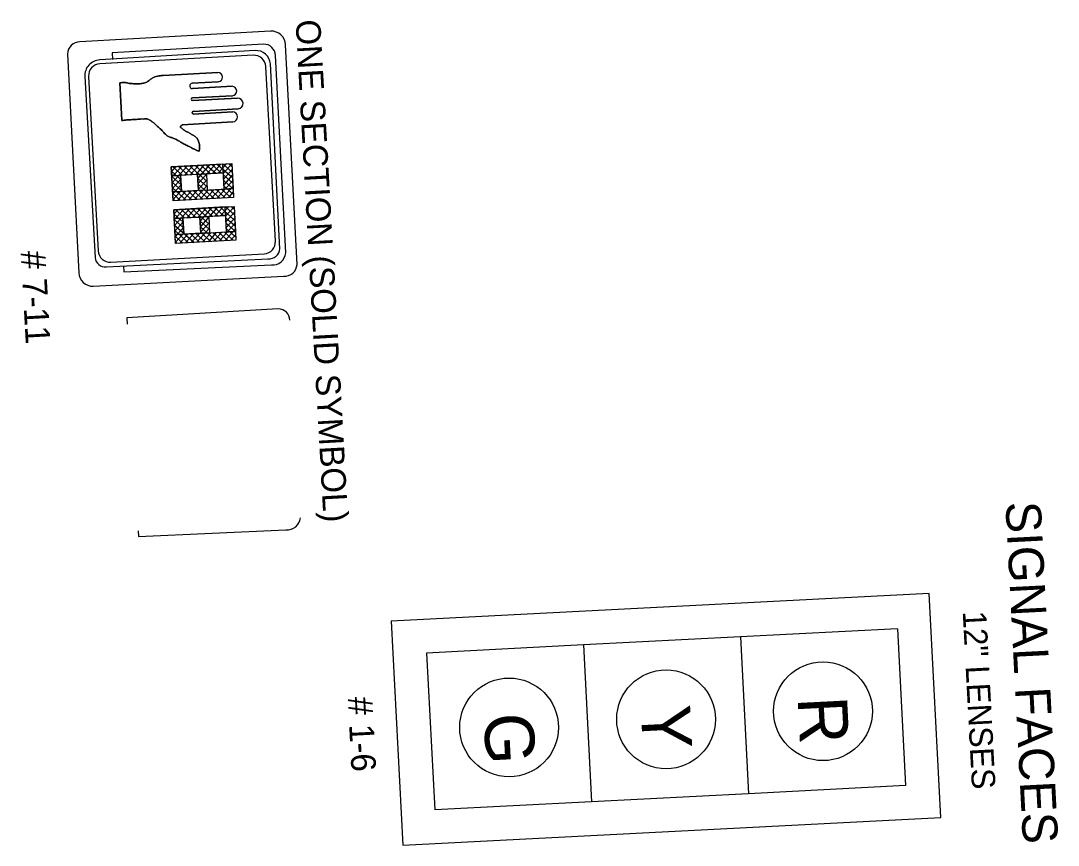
# Model space of a CAD drawing. Extents: x -218554 to 420114, y -565956 to -483460.
# Drawn here: x -218285.8 to -218207.2, y -484168.8 to -484106.3 of the extents above; entities that cross this region are included whole.
import ezdxf

# ---------------------------------------------------------------- set-up
doc = ezdxf.new("R2010")
doc.units = 0
for name, color, linetype in [('C-ANNO-TEXT', 7, 'Continuous'), ('Level 1', 7, 'Continuous'), ('Level 61', 7, 'Continuous')]:
    doc.layers.add(name, color=color, linetype=linetype)

msp = doc.modelspace()

# ---------------------------------------------------------------- linework, layer by layer
at = {"layer": 'Level 1'}
for p, q in [((-218266.858, -484107.089), (-218281.297, -484107.896)), ((-218264.85, -484124.763), (-218265.721, -484108.12)), ((-218282.226, -484108.821), (-218281.371, -484125.397)), ((-218268.029, -484108.558), (-218279.793, -484109.264)), ((-218265.704, -484123.89), (-218266.495, -484108.923)), ((-218266.149, -484123.569), (-218266.874, -484109.566)), ((-218280.924, -484110.527), (-218280.144, -484124.236)), ((-218274.981, -484110.441), (-218270.845, -484110.213)), ((-218270.845, -484110.213), (-218274.981, -484110.441)), ((-218278.123, -484113.841), (-218278.279, -484111.01)), ((-218278.264, -484110.994), (-218278.124, -484113.853)), ((-218270.814, -484110.923), (-218272.786, -484111.031)), ((-218272.786, -484111.031), (-218270.814, -484110.923)), ((-218272.764, -484111.431), (-218269.772, -484111.266)), ((-218269.772, -484111.266), (-218272.764, -484111.431)), ((-218272.779, -484112.349), (-218269.354, -484112.16)), ((-218269.354, -484112.16), (-218272.779, -484112.349)), ((-218269.741, -484111.977), (-218272.775, -484112.144)), ((-218272.775, -484112.144), (-218269.741, -484111.977)), ((-218272.707, -484113.367), (-218269.722, -484113.203)), ((-218269.722, -484113.203), (-218272.707, -484113.367)), ((-218269.301, -484112.975), (-218272.702, -484113.162)), ((-218272.702, -484113.162), (-218269.301, -484112.975)), ((-218278.126, -484113.855), (-218278.123, -484113.841)), ((-218269.705, -484113.964), (-218273.547, -484114.175)), ((-218273.547, -484114.175), (-218269.705, -484113.964)), ((-218271.049, -484117.19), (-218272.344, -484118.636)), ((-218270.624, -484117.167), (-218271.253, -484117.869)), ((-218270.863, -484117.18), (-218269.742, -484118.184)), ((-218270.2, -484117.144), (-218270.829, -484117.846)), ((-218270.438, -484117.157), (-218269.766, -484117.759)), ((-218269.799, -484117.147), (-218270.428, -484117.85)), ((-218270.014, -484117.133), (-218269.789, -484117.335)), ((-218274.355, -484117.686), (-218273.652, -484118.315)), ((-218274.021, -484117.354), (-218274.352, -484117.724)), ((-218273.596, -484117.331), (-218274.329, -484118.149)), ((-218273.172, -484117.307), (-218274.306, -484118.573)), ((-218274.259, -484117.367), (-218273.557, -484117.996)), ((-218273.835, -484117.344), (-218273.133, -484117.973)), ((-218273.41, -484117.32), (-218272.708, -484117.949)), ((-218272.747, -484117.284), (-218273.376, -484117.986)), ((-218272.986, -484117.297), (-218271.686, -484118.462)), ((-218272.323, -484117.261), (-218272.952, -484117.963)), ((-218272.561, -484117.274), (-218271.709, -484118.037)), ((-218271.898, -484117.237), (-218272.527, -484117.94)), ((-218272.382, -484117.932), (-218272.315, -484119.162)), ((-218271.473, -484117.214), (-218272.367, -484118.212)), ((-218272.137, -484117.25), (-218271.434, -484117.879)), ((-218271.717, -484117.895), (-218271.649, -484119.125)), ((-218271.712, -484117.227), (-218271.01, -484117.856)), ((-218271.287, -484117.204), (-218270.585, -484117.833)), ((-218270.421, -484117.979), (-218269.719, -484118.608)), ((-218269.776, -484117.572), (-218270.405, -484118.274)), ((-218274.331, -484118.11), (-218273.629, -484118.739)), ((-218274.308, -484118.535), (-218272.831, -484119.858)), ((-218273.653, -484118.296), (-218274.282, -484118.998)), ((-218273.63, -484118.72), (-218274.259, -484119.423)), ((-218272.365, -484118.257), (-218271.662, -484118.886)), ((-218272.341, -484118.682), (-218271.132, -484119.764)), ((-218271.691, -484118.358), (-218272.32, -484119.061)), ((-218269.729, -484118.421), (-218270.922, -484119.752)), ((-218270.398, -484118.404), (-218269.696, -484119.033)), ((-218269.753, -484117.996), (-218270.382, -484118.699)), ((-218274.284, -484118.959), (-218273.255, -484119.881)), ((-218274.261, -484119.384), (-218273.68, -484119.904)), ((-218273.606, -484119.145), (-218274.235, -484119.847)), ((-218273.265, -484119.214), (-218273.894, -484119.916)), ((-218272.84, -484119.19), (-218273.469, -484119.893)), ((-218273.109, -484119.205), (-218272.406, -484119.834)), ((-218272.416, -484119.167), (-218273.045, -484119.869)), ((-218272.684, -484119.182), (-218271.982, -484119.811)), ((-218271.668, -484118.783), (-218272.62, -484119.846)), ((-218272.318, -484119.106), (-218271.557, -484119.787)), ((-218271.566, -484119.12), (-218272.195, -484119.823)), ((-218271.142, -484119.097), (-218271.771, -484119.799)), ((-218271.41, -484119.112), (-218270.708, -484119.741)), ((-218270.717, -484119.074), (-218271.346, -484119.776)), ((-218270.986, -484119.088), (-218270.283, -484119.717)), ((-218270.561, -484119.065), (-218269.859, -484119.694)), ((-218269.706, -484118.846), (-218270.497, -484119.729)), ((-218270.375, -484118.828), (-218269.672, -484119.457)), ((-218269.683, -484119.27), (-218270.073, -484119.706)), ((-218274.238, -484119.809), (-218274.104, -484119.928)), ((-218274.176, -484120.923), (-218273.474, -484121.552)), ((-218273.843, -484120.591), (-218274.174, -484120.962)), ((-218273.418, -484120.568), (-218274.151, -484121.386)), ((-218272.993, -484120.545), (-218274.127, -484121.811)), ((-218274.081, -484120.605), (-218273.379, -484121.234)), ((-218273.657, -484120.581), (-218272.954, -484121.21)), ((-218273.232, -484120.558), (-218272.53, -484121.187)), ((-218272.569, -484120.521), (-218273.198, -484121.224)), ((-218272.807, -484120.534), (-218271.507, -484121.699)), ((-218272.144, -484120.498), (-218272.773, -484121.2)), ((-218272.383, -484120.511), (-218271.531, -484121.274)), ((-218271.72, -484120.475), (-218272.349, -484121.177)), ((-218271.295, -484120.451), (-218272.189, -484121.449)), ((-218270.871, -484120.428), (-218272.165, -484121.873)), ((-218271.958, -484120.488), (-218271.256, -484121.117)), ((-218271.534, -484120.464), (-218270.831, -484121.093)), ((-218271.109, -484120.441), (-218270.407, -484121.07)), ((-218270.446, -484120.404), (-218271.075, -484121.107)), ((-218270.685, -484120.418), (-218269.564, -484121.421)), ((-218270.022, -484120.381), (-218270.651, -484121.083)), ((-218270.26, -484120.394), (-218269.587, -484120.997)), ((-218269.621, -484120.385), (-218270.25, -484121.087)), ((-218269.598, -484120.809), (-218270.227, -484121.511)), ((-218269.835, -484120.371), (-218269.611, -484120.572)), ((-218274.153, -484121.348), (-218273.451, -484121.977)), ((-218274.129, -484121.772), (-218272.652, -484123.095)), ((-218273.475, -484121.533), (-218274.104, -484122.235)), ((-218272.204, -484121.169), (-218272.136, -484122.399)), ((-218272.186, -484121.494), (-218271.484, -484122.123)), ((-218271.513, -484121.596), (-218272.142, -484122.298)), ((-218271.538, -484121.132), (-218271.471, -484122.362)), ((-218269.551, -484121.658), (-218270.743, -484122.99)), ((-218270.243, -484121.217), (-218269.541, -484121.846)), ((-218270.22, -484121.641), (-218269.517, -484122.27)), ((-218269.574, -484121.234), (-218270.203, -484121.936)), ((-218274.106, -484122.197), (-218273.077, -484123.118)), ((-218274.083, -484122.621), (-218273.502, -484123.142)), ((-218273.452, -484121.958), (-218274.081, -484122.66)), ((-218273.428, -484122.382), (-218274.057, -484123.084)), ((-218273.086, -484122.451), (-218273.715, -484123.153)), ((-218272.662, -484122.428), (-218273.291, -484123.13)), ((-218272.93, -484122.443), (-218272.228, -484123.072)), ((-218272.237, -484122.404), (-218272.866, -484123.107)), ((-218272.506, -484122.419), (-218271.803, -484123.048)), ((-218271.49, -484122.02), (-218272.442, -484123.083)), ((-218272.163, -484121.919), (-218270.954, -484123.001)), ((-218272.139, -484122.343), (-218271.379, -484123.025)), ((-218271.388, -484122.358), (-218272.017, -484123.06)), ((-218270.964, -484122.334), (-218271.593, -484123.037)), ((-218271.232, -484122.349), (-218270.53, -484122.978)), ((-218270.539, -484122.311), (-218271.168, -484123.013)), ((-218270.807, -484122.326), (-218270.105, -484122.955)), ((-218270.383, -484122.302), (-218269.681, -484122.931)), ((-218269.528, -484122.083), (-218270.319, -484122.966)), ((-218270.196, -484122.066), (-218269.494, -484122.695)), ((-218269.504, -484122.507), (-218269.894, -484122.943)), ((-218274.059, -484123.046), (-218273.926, -484123.165)), ((-218279.286, -484124.948), (-218267.051, -484124.332)), ((-218280.29, -484126.408), (-218265.861, -484125.648))]:
    msp.add_line(p, q, dxfattribs=at)
for points in [[(-218267.382, -484108.074), (-218278.854, -484108.74), (-218278.828, -484109.222)], [(-218268.174, -484108.914), (-218279.777, -484109.553)], [(-218266.488, -484122.997), (-218267.216, -484109.772)], [(-218280.635, -484110.511), (-218279.907, -484123.736)], [(-218272.315, -484119.162), (-218273.602, -484119.232), (-218273.669, -484118.002), (-218272.382, -484117.932)], [(-218271.649, -484119.125), (-218270.362, -484119.054), (-218270.43, -484117.824), (-218271.717, -484117.895)], [(-218271.471, -484122.362), (-218270.184, -484122.291), (-218270.252, -484121.061), (-218271.538, -484121.132)], [(-218272.136, -484122.399), (-218273.423, -484122.47), (-218273.491, -484121.24), (-218272.204, -484121.169)], [(-218278.949, -484124.593), (-218267.345, -484123.954)], [(-218277.999, -484124.874), (-218277.975, -484125.308), (-218266.795, -484124.802)], [(-218266.278, -484128.135), (-218277.749, -484128.801), (-218277.723, -484129.283)], [(-218276.895, -484144.935), (-218276.87, -484145.369), (-218265.69, -484144.863)]]:
    msp.add_lwpolyline(points, dxfattribs=at)
for points in [[(-218269.801, -484117.122), (-218269.66, -484119.683), (-218274.231, -484119.935), (-218274.372, -484117.373)], [(-218274.372, -484117.373), (-218274.337, -484118.029), (-218270.43, -484117.824), (-218270.464, -484117.169)], [(-218269.801, -484117.122), (-218269.701, -484119.019), (-218270.362, -484119.054), (-218270.461, -484117.156)], [(-218271.717, -484117.895), (-218271.652, -484119.127), (-218272.315, -484119.162), (-218272.379, -484117.93)], [(-218273.669, -484118.002), (-218273.605, -484119.224), (-218274.266, -484119.258), (-218274.33, -484118.037)], [(-218269.701, -484119.019), (-218269.666, -484119.696), (-218274.231, -484119.935), (-218274.266, -484119.258)], [(-218269.623, -484120.359), (-218269.481, -484122.92), (-218274.052, -484123.172), (-218274.193, -484120.611)], [(-218274.193, -484120.611), (-218274.159, -484121.266), (-218270.252, -484121.061), (-218270.286, -484120.406)], [(-218269.623, -484120.359), (-218269.523, -484122.257), (-218270.184, -484122.291), (-218270.283, -484120.394)], [(-218273.491, -484121.24), (-218273.427, -484122.461), (-218274.088, -484122.496), (-218274.152, -484121.274)], [(-218271.538, -484121.132), (-218271.474, -484122.364), (-218272.136, -484122.399), (-218272.201, -484121.167)], [(-218269.523, -484122.257), (-218269.488, -484122.933), (-218274.052, -484123.172), (-218274.088, -484122.496)]]:
    msp.add_lwpolyline(points, close=True, dxfattribs=at)
for centre, radius, start, end in [((-218266.806, -484108.173), 1.086, 2.77432, 92.77432), ((-218281.298, -484108.823), 0.927, 89.93321, 179.93321), ((-218267.363, -484108.942), 0.869, 1.27514, 91.27514), ((-218279.727, -484110.461), 1.198, 93.15216, 183.15216), ((-218268.124, -484109.822), 0.909, 3.15216, 93.15216), ((-218267.955, -484109.639), 1.083, 3.88192, 93.88192), ((-218279.727, -484110.461), 0.909, 93.15216, 183.15216), ((-218270.85, -484110.568), 0.356, 275.81971, 89.16653), ((-218270.85, -484110.568), 0.356, 275.81971, 89.16653), ((-218272.776, -484111.231), 0.2, 93.15216, 273.15216), ((-218272.776, -484111.231), 0.2, 93.15216, 273.15216), ((-218269.777, -484111.622), 0.356, 275.81971, 89.16653), ((-218269.777, -484111.622), 0.356, 275.81971, 89.16653), ((-218272.777, -484112.246), 0.102, 88.57477, 268.57477), ((-218272.777, -484112.246), 0.102, 88.57477, 268.57477), ((-218269.351, -484112.569), 0.409, 277.05213, 90.39894), ((-218269.351, -484112.569), 0.409, 277.05213, 90.39894), ((-218272.704, -484113.263), 0.104, 88.04746, 268.04746), ((-218272.704, -484113.263), 0.104, 88.04746, 268.04746), ((-218269.736, -484113.584), 0.381, 274.62974, 87.97656), ((-218269.736, -484113.584), 0.381, 274.62974, 87.97656), ((-218267.396, -484123.047), 0.909, 273.15216, 3.15216), ((-218279.359, -484124.163), 0.788, 185.26181, 275.26181), ((-218278.999, -484123.686), 0.909, 183.15216, 273.15216), ((-218266.982, -484123.499), 0.836, 265.22621, 355.22621), ((-218266.706, -484123.8), 1.005, 264.91062, 354.91062), ((-218265.798, -484124.7), 0.95, 266.18024, 356.18024), ((-218280.324, -484125.362), 1.047, 181.91264, 271.91264), ((-218266.259, -484129.003), 0.869, 1.27514, 91.27514), ((-218265.601, -484143.861), 1.005, 264.91062, 354.91062)]:
    msp.add_arc(centre, radius, start, end, dxfattribs=at)
for points in [[(-218278.264, -484110.994), (-218278.107, -484110.985), (-218277.841, -484110.981), (-218277.562, -484111.044), (-218277.246, -484111.066), (-218277.068, -484111.086), (-218276.724, -484111.067), (-218276.441, -484111.022), (-218276.296, -484110.984), (-218276.057, -484110.823), (-218275.821, -484110.653), (-218275.62, -484110.553), (-218275.406, -484110.502), (-218275.241, -484110.464), (-218275.134, -484110.458), (-218274.981, -484110.441)], [(-218274.981, -484110.441), (-218275.134, -484110.458), (-218275.241, -484110.464), (-218275.406, -484110.502), (-218275.62, -484110.553), (-218275.821, -484110.653), (-218276.057, -484110.823), (-218276.296, -484110.984), (-218276.441, -484111.022), (-218276.724, -484111.067), (-218277.068, -484111.086), (-218277.246, -484111.066), (-218277.562, -484111.044), (-218277.841, -484110.981), (-218278.107, -484110.985), (-218278.264, -484110.994)], [(-218273.546, -484114.173), (-218273.55, -484114.202), (-218273.627, -484114.245), (-218273.684, -484114.297), (-218273.691, -484114.327), (-218273.68, -484114.376), (-218273.638, -484114.403), (-218273.535, -484114.487), (-218273.453, -484114.55), (-218273.392, -484114.586), (-218273.341, -484114.623), (-218273.249, -484114.688), (-218273.168, -484114.721), (-218273.057, -484114.775), (-218272.996, -484114.81), (-218272.884, -484114.873), (-218272.781, -484114.946), (-218272.68, -484115), (-218272.578, -484115.063), (-218272.506, -484115.118), (-218272.423, -484115.202), (-218272.377, -484115.308), (-218272.344, -484115.365), (-218272.311, -484115.452), (-218272.277, -484115.528), (-218272.25, -484115.646), (-218272.245, -484115.744), (-218272.238, -484115.871), (-218272.241, -484115.989), (-218272.253, -484116.127), (-218272.271, -484116.168), (-218272.299, -484116.179), (-218272.43, -484116.127), (-218272.501, -484116.092), (-218272.573, -484116.057), (-218272.653, -484116.022), (-218272.703, -484116.005), (-218272.835, -484115.933), (-218273.019, -484115.825), (-218273.312, -484115.683), (-218273.646, -484115.505), (-218273.881, -484115.361), (-218274.033, -484115.28), (-218274.174, -484115.21), (-218274.287, -484115.171), (-218274.344, -484115.15), (-218274.586, -484115.076), (-218274.76, -484114.947), (-218274.884, -484114.846), (-218275.01, -484114.695), (-218275.085, -484114.601), (-218275.354, -484114.36), (-218275.581, -484114.146), (-218275.737, -484114.007), (-218275.91, -484113.889), (-218275.987, -484113.83), (-218276.095, -484113.781), (-218276.195, -484113.728), (-218276.412, -484113.74), (-218276.606, -484113.74), (-218276.783, -484113.75), (-218277.018, -484113.773), (-218277.244, -484113.786), (-218277.607, -484113.806), (-218277.9, -484113.831), (-218278.007, -484113.846), (-218278.086, -484113.851), (-218278.124, -484113.853)], [(-218278.124, -484113.853), (-218278.086, -484113.851), (-218278.007, -484113.846), (-218277.9, -484113.831), (-218277.607, -484113.806), (-218277.244, -484113.786), (-218277.018, -484113.773), (-218276.783, -484113.75), (-218276.606, -484113.74), (-218276.412, -484113.74), (-218276.195, -484113.728), (-218276.095, -484113.781), (-218275.987, -484113.83), (-218275.91, -484113.889), (-218275.737, -484114.007), (-218275.581, -484114.146), (-218275.354, -484114.36), (-218275.085, -484114.601), (-218275.01, -484114.695), (-218274.884, -484114.846), (-218274.76, -484114.947), (-218274.586, -484115.076), (-218274.344, -484115.15), (-218274.287, -484115.171), (-218274.174, -484115.21), (-218274.033, -484115.28), (-218273.881, -484115.361), (-218273.646, -484115.505), (-218273.312, -484115.683), (-218273.019, -484115.825), (-218272.835, -484115.933), (-218272.703, -484116.005), (-218272.653, -484116.022), (-218272.573, -484116.057), (-218272.501, -484116.092), (-218272.43, -484116.127), (-218272.299, -484116.179), (-218272.271, -484116.168), (-218272.253, -484116.127), (-218272.241, -484115.989), (-218272.238, -484115.871), (-218272.245, -484115.744), (-218272.25, -484115.646), (-218272.277, -484115.528), (-218272.311, -484115.452), (-218272.344, -484115.365), (-218272.377, -484115.308), (-218272.423, -484115.202), (-218272.506, -484115.118), (-218272.578, -484115.063), (-218272.68, -484115), (-218272.781, -484114.946), (-218272.884, -484114.873), (-218272.996, -484114.81), (-218273.057, -484114.775), (-218273.168, -484114.721), (-218273.249, -484114.688), (-218273.341, -484114.623), (-218273.392, -484114.586), (-218273.453, -484114.55), (-218273.535, -484114.487), (-218273.638, -484114.403), (-218273.68, -484114.376), (-218273.691, -484114.327), (-218273.684, -484114.297), (-218273.627, -484114.245), (-218273.55, -484114.202), (-218273.546, -484114.173)]]:
    msp.add_spline(points, degree=3, dxfattribs=at)
at = {"layer": 'Level 61'}
for p, q in [((-218219.388, -484152.359), (-218231.273, -484152.972)), ((-218219.388, -484152.359), (-218218.775, -484164.243)), ((-218231.273, -484152.972), (-218243.158, -484153.585)), ((-218231.273, -484152.972), (-218230.66, -484164.857)), ((-218243.158, -484153.585), (-218255.043, -484154.198)), ((-218243.158, -484153.585), (-218242.545, -484165.47)), ((-218255.043, -484154.198), (-218254.43, -484166.083)), ((-218218.775, -484164.243), (-218230.66, -484164.857)), ((-218230.66, -484164.857), (-218242.545, -484165.47)), ((-218242.545, -484165.47), (-218254.43, -484166.083))]:
    msp.add_line(p, q, dxfattribs=at)
msp.add_lwpolyline([(-218256.845, -484168.761), (-218216.097, -484166.659), (-218216.973, -484149.68), (-218257.721, -484151.783)], close=True, dxfattribs=at)
for centre in [(-218225.024, -484158.608), (-218236.909, -484159.221), (-218248.794, -484159.834)]:
    msp.add_circle(centre, 3.74, dxfattribs=at)

# ---------------------------------------------------------------- texts
at = {"layer": 'C-ANNO-TEXT'}
for s, height, rotation, p in [('ONE SECTION (SOLID SYMBOL)', 1.86667, 273.19877, (-218264.965, -484106.257)), ('# 7-11', 1.8667, 273.19877, (-218285.782, -484123.777)), ('# 1-6', 1.8667, 272.95326, (-218261.016, -484157.549))]:
    msp.add_text(s, height=height, rotation=rotation, dxfattribs=at).set_placement(p)
at = {"layer": 'Level 61'}
for s, height, rotation, p in [('SIGNAL FACES', 2.66667, 272.95326, (-218211.212, -484142.781)), ('12" LENSES', 1.7778, 273.02529, (-218214.447, -484151.051)), ('R', 3.739, 272.95326, (-218226.95, -484157.574)), ('Y', 3.739, 272.95326, (-218238.832, -484158.231)), ('G', 3.739, 272.95326, (-218250.718, -484158.833))]:
    msp.add_text(s, height=height, rotation=rotation, dxfattribs=at).set_placement(p)

doc.saveas('drawing.dxf')
